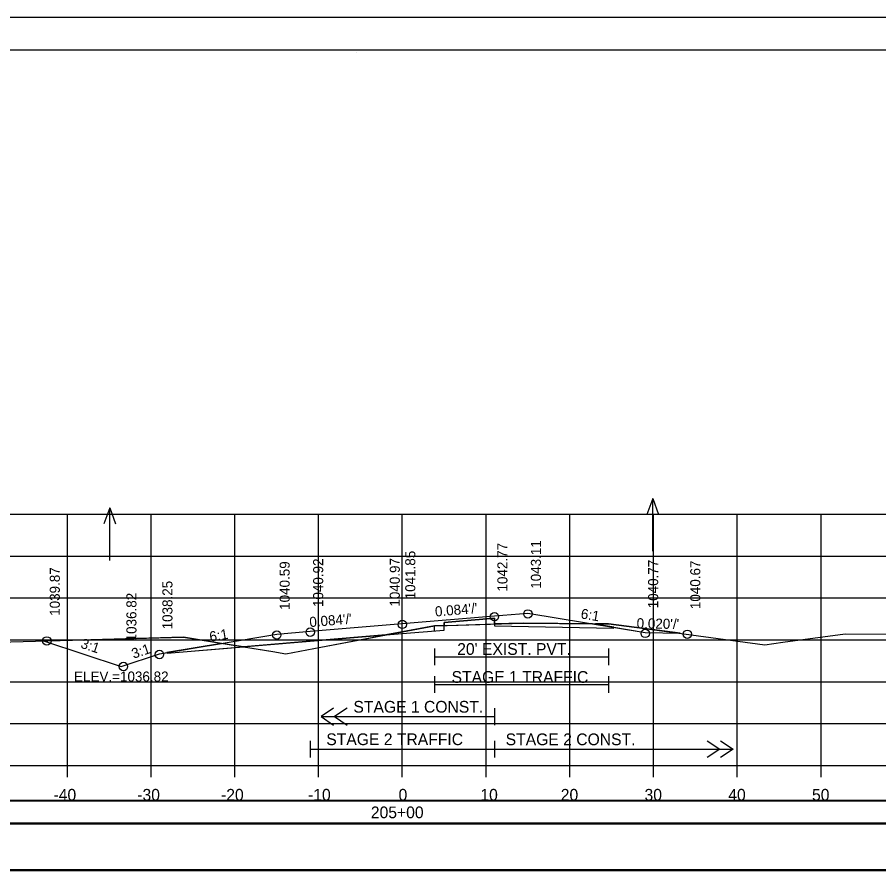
# Model space of a CAD drawing. Extents: x 1370565 to 1374448, y 301010 to 304637.
# Drawn here: x 1373322.8 to 1373425.7, y 301408.9 to 301511.7 of the extents above; entities that cross this region are included whole.
import ezdxf

# ---------------------------------------------------------------- set-up
doc = ezdxf.new("R2010")
doc.units = 0
for name, color, linetype in [('Default', 7, 'Continuous'), ('R_Alt Surface', 7, 'Continuous'), ('R_Axis', 7, 'Continuous'), ('R_Axis Annot', 7, 'Continuous'), ('R_Border', 7, 'Continuous'), ('R_Contours', 7, 'Continuous'), ('R_Drive', 7, 'Continuous'), ('R_Exist Surface', 7, 'Continuous'), ('R_Fin Surface', 7, 'Continuous'), ('R_Grid', 7, 'Continuous'), ('R_No Plot', 7, 'Continuous'), ('R_Water', 7, 'Continuous'), ('R_Water Annot', 7, 'Continuous'), ('R_Xsect Elev', 7, 'Continuous'), ('R_Xsect Slope', 7, 'Continuous')]:
    doc.layers.add(name, color=color, linetype=linetype)

msp = doc.modelspace()

# ---------------------------------------------------------------- linework, layer by layer
at = {"layer": 'Default'}
for points in [[(1373219.61, 301415.34), (1373518.02, 301415.34), (1373518.02, 301418.04), (1373219.61, 301418.04)], [(1373219.61, 301409.76), (1373518.02, 301409.76), (1373518.02, 301415.28), (1373219.61, 301415.28)]]:
    msp.add_lwpolyline(points, close=True, dxfattribs=at)
at = {"layer": 'R_Alt Surface'}
for points in [[(1373340.71, 301435.7), (1373357.81, 301437.14), (1373368.81, 301438.06), (1373373.81, 301438.47), (1373373.81, 301439.39), (1373379.81, 301439.9), (1373379.82, 301438.98), (1373379.81, 301438.98), (1373394.03, 301438.7)], [(1373360.61, 301429.13), (1373359.11, 301428.13), (1373360.61, 301427.13)], [(1373362.21, 301429.13), (1373360.71, 301428.13), (1373362.21, 301427.13)], [(1373359.11, 301428.13), (1373379.81, 301428.13)], [(1373357.81, 301425.26), (1373357.81, 301423.26)], [(1373379.81, 301425.26), (1373379.81, 301423.26)], [(1373379.81, 301425.26), (1373379.81, 301423.26)], [(1373405.21, 301425.26), (1373406.71, 301424.26), (1373405.21, 301423.26)], [(1373406.8, 301425.26), (1373408.3, 301424.26), (1373406.8, 301423.26)], [(1373357.81, 301424.26), (1373379.81, 301424.26)], [(1373379.81, 301424.26), (1373408.3, 301424.26)]]:
    msp.add_lwpolyline(points, dxfattribs=at)
at = {"layer": 'R_Axis'}
for p, q in [((1373218.81, 301422.3), (1373518.81, 301422.3)), ((1373328.81, 301420.9), (1373328.81, 301422.3)), ((1373338.81, 301420.9), (1373338.81, 301422.3)), ((1373348.81, 301420.9), (1373348.81, 301422.3)), ((1373358.81, 301420.9), (1373358.81, 301422.3)), ((1373368.81, 301420.9), (1373368.81, 301422.3)), ((1373378.81, 301420.9), (1373378.81, 301422.3)), ((1373388.81, 301420.9), (1373388.81, 301422.3)), ((1373398.81, 301420.9), (1373398.81, 301422.3)), ((1373408.81, 301420.9), (1373408.81, 301422.3)), ((1373418.81, 301420.9), (1373418.81, 301422.3))]:
    msp.add_line(p, q, dxfattribs=at)
for points in [[(1373372.67, 301436.28), (1373372.67, 301434.28)], [(1373393.43, 301436.28), (1373393.43, 301434.28)], [(1373372.67, 301435.28), (1373393.43, 301435.28)], [(1373372.67, 301432.96), (1373372.67, 301430.96)], [(1373393.43, 301432.96), (1373393.43, 301430.96)], [(1373372.67, 301431.96), (1373393.43, 301431.96)], [(1373379.81, 301429.13), (1373379.81, 301427.13)]]:
    msp.add_lwpolyline(points, dxfattribs=at)
at = {"layer": 'R_Border'}
for p, q in [((1373210.81, 301507.76), (1373526.99, 301507.76)), ((1373363.33, 301507.5), (1373363.33, 301507.5)), ((1373363.33, 301507.5), (1373363.33, 301507.5))]:
    msp.add_line(p, q, dxfattribs=at)
at = {"layer": 'R_Contours'}
for p, q in [((1373372.67, 301438.38), (1373372.67, 301438.99)), ((1373379.82, 301439.2), (1373379.81, 301439.9)), ((1373391.85, 301439.16), (1373391.51, 301439.22)), ((1373394.05, 301438.8), (1373391.85, 301439.16)), ((1373366.82, 301437.89), (1373368.81, 301438.06)), ((1373397.81, 301438.17), (1373401.98, 301438.09)), ((1373357.81, 301437.14), (1373349.85, 301436.47)), ((1373366.82, 301437.89), (1373357.81, 301437.14)), ((1373347.23, 301436.88), (1373340.7, 301435.8)), ((1373340.71, 301435.7), (1373349.85, 301436.47)), ((1373349.85, 301436.47), (1373347.23, 301436.88))]:
    msp.add_line(p, q, dxfattribs=at)
for points in [[(1373373.81, 301439.02), (1373372.67, 301438.99), (1373368.81, 301438.27), (1373366.82, 301437.89)], [(1373368.81, 301438.06), (1373373.81, 301438.47), (1373373.81, 301439.02)], [(1373379.81, 301439.9), (1373373.81, 301439.39), (1373373.81, 301439.02)], [(1373373.81, 301439.02), (1373374.17, 301439.03), (1373379.82, 301439.2)], [(1373391.51, 301439.22), (1373383.25, 301439.29), (1373379.82, 301439.2)], [(1373379.82, 301439.2), (1373379.82, 301438.98), (1373394.03, 301438.7)], [(1373391.86, 301439.22), (1373391.85, 301439.16)], [(1373391.85, 301439.16), (1373394.05, 301438.8), (1373397.81, 301438.17)], [(1373401.98, 301438.09), (1373397.72, 301438.66), (1373393.43, 301439.2), (1373391.86, 301439.22)], [(1373394.03, 301438.7), (1373394.05, 301438.8)], [(1373347.23, 301436.88), (1373342.67, 301437.61), (1373326.09, 301437.16)], [(1373326.09, 301437.16), (1373335.22, 301434.12), (1373339.81, 301435.65), (1373340.7, 301435.8), (1373347.23, 301436.88)], [(1373349.85, 301436.47), (1373353.33, 301435.92), (1373354.89, 301435.65), (1373359.09, 301436.44), (1373366.82, 301437.89)], [(1373340.7, 301435.8), (1373340.71, 301435.7)]]:
    msp.add_lwpolyline(points, dxfattribs=at)
at = {"layer": 'R_Drive'}
for points in [[(1373219.61, 301415.39), (1373518.02, 301415.39), (1373518.02, 301418.1), (1373219.61, 301418.1)], [(1373219.61, 301409.87), (1373518.02, 301409.87), (1373518.02, 301415.39), (1373219.61, 301415.39)]]:
    msp.add_lwpolyline(points, close=True, dxfattribs=at)
at = {"layer": 'R_Exist Surface'}
msp.add_lwpolyline([(1373304.34, 301436.57), (1373342.67, 301437.61), (1373353.33, 301435.92), (1373354.89, 301435.65), (1373359.09, 301436.44), (1373372.67, 301438.99), (1373374.17, 301439.03), (1373383.25, 301439.29), (1373391.86, 301439.22), (1373393.43, 301439.2), (1373397.72, 301438.66), (1373412.1, 301436.72), (1373414.24, 301437.01), (1373421.68, 301438.02), (1373448.35, 301437.96), (1373476.27, 301437.85), (1373489.59, 301438.27), (1373490.01, 301438.26), (1373491.15, 301438.32), (1373493.83, 301438.43), (1373507.3, 301439.28), (1373514.72, 301439.44), (1373518.02, 301439.57), (1373518.81, 301439.61)], dxfattribs=at)
at = {"layer": 'R_Fin Surface'}
msp.add_lwpolyline([(1373326.09, 301437.16), (1373335.22, 301434.12), (1373339.81, 301435.65), (1373353.81, 301437.98), (1373357.81, 301438.32), (1373368.81, 301439.24), (1373379.81, 301440.17), (1373383.81, 301440.5), (1373397.81, 301438.17), (1373401.98, 301438.09)], dxfattribs=at)
at = {"layer": 'R_Grid'}
for p, q in [((1373218.81, 301452.3), (1373518.81, 301452.3)), ((1373328.81, 301422.3), (1373328.81, 301452.3)), ((1373338.81, 301422.3), (1373338.81, 301452.3)), ((1373348.81, 301422.3), (1373348.81, 301452.3)), ((1373358.81, 301422.3), (1373358.81, 301452.3)), ((1373368.81, 301422.3), (1373368.81, 301452.3)), ((1373378.81, 301422.3), (1373378.81, 301452.3)), ((1373388.81, 301422.3), (1373388.81, 301452.3)), ((1373398.81, 301422.3), (1373398.81, 301452.3)), ((1373408.81, 301422.3), (1373408.81, 301452.3)), ((1373418.81, 301422.3), (1373418.81, 301452.3)), ((1373218.81, 301447.3), (1373518.81, 301447.3)), ((1373218.81, 301442.3), (1373518.81, 301442.3)), ((1373218.81, 301437.3), (1373518.81, 301437.3)), ((1373218.81, 301432.3), (1373518.81, 301432.3)), ((1373218.81, 301427.3), (1373518.81, 301427.3)), ((1373218.81, 301422.3), (1373518.81, 301422.3))]:
    msp.add_line(p, q, dxfattribs=at)
at = {"layer": 'R_No Plot'}
msp.add_line((1373198.41, 301511.65), (1373531.75, 301511.65), dxfattribs=at)
for points in [[(1373198.41, 301511.65), (1373531.75, 301511.65), (1373531.75, 301298.32), (1373198.41, 301298.32)], [(1373444.73, 301507.76), (1373464.35, 301507.76), (1373464.35, 301497.88), (1373480.47, 301497.88), (1373503.67, 301497.88), (1373503.67, 301473.55), (1373526.99, 301473.55), (1373526.99, 301302.3), (1373210.81, 301302.3), (1373210.81, 301507.76)]]:
    msp.add_lwpolyline(points, close=True, dxfattribs=at)
for centre in [(1373379.81, 301440.07), (1373383.81, 301440.4), (1373368.81, 301439.14), (1373353.81, 301437.88), (1373357.81, 301438.22), (1373397.81, 301438.07), (1373402.84, 301437.97), (1373326.36, 301437.17), (1373339.81, 301435.55), (1373335.51, 301434.12)]:
    msp.add_circle(centre, 0.5, dxfattribs=at)
at = {"layer": 'R_Water Annot'}
for p, q in [((1373398.71, 301454.2), (1373398.01, 301452.27)), ((1373398.71, 301447.91), (1373398.71, 301454.2)), ((1373398.71, 301454.2), (1373399.41, 301452.27)), ((1373333.87, 301453.08), (1373333.17, 301451.15)), ((1373333.87, 301446.79), (1373333.87, 301453.08)), ((1373333.87, 301453.08), (1373334.57, 301451.15))]:
    msp.add_line(p, q, dxfattribs=at)
at = {"layer": 'R_Xsect Elev'}
msp.add_line((1373368.81, 301438.27), (1373368.81, 301448.27), dxfattribs=at)

# ---------------------------------------------------------------- texts
at = {"layer": 'R_Axis Annot'}
for s, p in [("20' EXIST. PVT.", (1373375.36, 301435.51)), ('-40', (1373327.16, 301418.1)), ('-30', (1373337.16, 301418.1)), ('-20', (1373347.16, 301418.1)), ('-10', (1373357.55, 301418.1)), ('0', (1373368.36, 301418.1)), ('10', (1373378.13, 301418.1)), ('20', (1373387.73, 301418.1)), ('30', (1373397.73, 301418.1)), ('40', (1373407.73, 301418.1)), ('50', (1373417.73, 301418.1)), ('205+00', (1373365.05, 301416))]:
    msp.add_text(s, height=1.4, dxfattribs=at).set_placement(p)
at = {"layer": 'R_Water'}
for s, p in [('STAGE 1 TRAFFIC', (1373374.69, 301432.17)), ('STAGE 1 CONST.', (1373362.97, 301428.61)), ('STAGE 2 TRAFFIC', (1373359.73, 301424.73)), ('STAGE 2 CONST.', (1373381.15, 301424.72))]:
    msp.add_text(s, height=1.4, dxfattribs=at).set_placement(p)
at = {"layer": 'R_Xsect Elev'}
for s, p in [('1042.77', (1373381.36, 301443.07)), ('1043.11', (1373385.36, 301443.4)), ('1041.85', (1373370.36, 301442.14)), ('1040.59', (1373355.36, 301440.88)), ('1040.92', (1373359.36, 301441.22)), ('1040.97', (1373368.51, 301441.27)), ('1040.77', (1373399.36, 301441.07)), ('1040.67', (1373404.39, 301440.97)), ('1039.87', (1373327.91, 301440.17)), ('1038.25', (1373341.36, 301438.55)), ('1036.82', (1373337.06, 301437.12))]:
    msp.add_text(s, height=1.2, rotation=90, dxfattribs=at).set_placement(p)
msp.add_text('ELEV.=1036.82', height=1.2, dxfattribs=at).set_placement((1373329.61, 301432.32))
at = {"layer": 'R_Xsect Slope'}
for s, rotation, p in [("0.084'/'", 4.8016, (1373372.76, 301440.08)), ("0.084'/'", 4.8016, (1373357.76, 301438.82)), ('6:1', 350.5358, (1373390.05, 301439.87)), ("0.020'/'", 358.8542, (1373396.78, 301438.69)), ('6:1', 9.4642, (1373345.88, 301437.07)), ('3:1', 341.5668, (1373330.31, 301436.38)), ('3:1', 18.4349, (1373336.72, 301435.04))]:
    msp.add_text(s, height=1.2, rotation=rotation, dxfattribs=at).set_placement(p)

doc.saveas('drawing.dxf')
